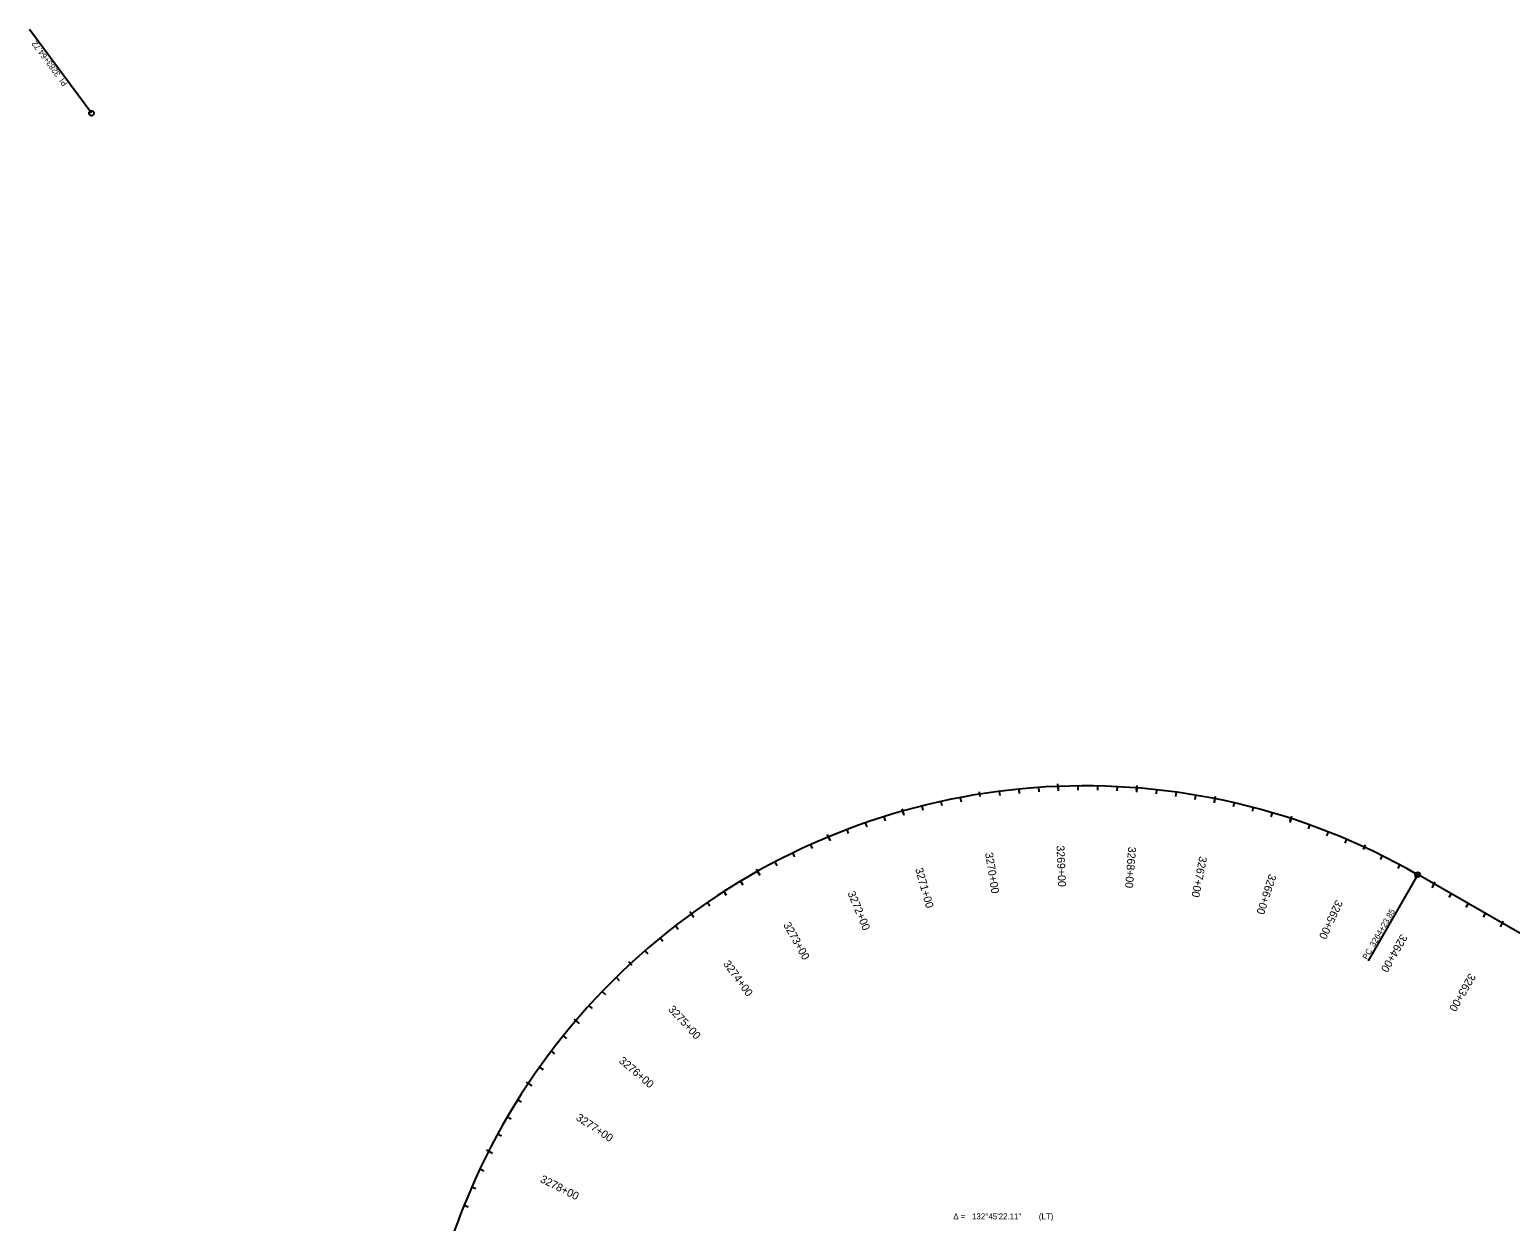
# Model space of a CAD drawing. Extents: x 15451313 to 15455081, y 8857737 to 8860760.
# Drawn here: x 15451313 to 15453192, y 8859247 to 8860760 of the extents above; entities that cross this region are included whole.
import ezdxf

# ---------------------------------------------------------------- set-up
doc = ezdxf.new("R2010")
doc.units = 0
for name, color, linetype in [('Annotation', 7, 'Continuous'), ('PC_REVISION_ANNOTATION', 7, 'Continuous'), ('SheetAddenda', 7, 'Continuous'), ('TextNonPlot', 7, 'Continuous')]:
    doc.layers.add(name, color=color, linetype=linetype)

msp = doc.modelspace()

# ---------------------------------------------------------------- linework, layer by layer
at = {"layer": 'Annotation'}
msp.add_line((15453768, 8859288.8), (15453074.6, 8859687), dxfattribs=at)
msp.add_arc((15452651.9, 8858950.9), 848.8, 60.1345, 192.8906, dxfattribs=at)
at = {"layer": 'PC_REVISION_ANNOTATION'}
for p, q in [((15452494.1, 8859784.9), (15452495.2, 8859779.5)), ((15452519.2, 8859786.2), (15452518.3, 8859792.2)), ((15452543.5, 8859792.7), (15452544.2, 8859787.3)), ((15452568.4, 8859795.6), (15452568.9, 8859790.1)), ((15452593.3, 8859797.7), (15452593.6, 8859792.2)), ((15452618.3, 8859796), (15452618.1, 8859802.1)), ((15452643.2, 8859799.6), (15452643.3, 8859794.2)), ((15452668.2, 8859799.5), (15452668.1, 8859794.1)), ((15452693.2, 8859798.7), (15452692.9, 8859793.2)), ((15452717.9, 8859794.1), (15452718.4, 8859800.2)), ((15452743, 8859794.8), (15452742.5, 8859789.4)), ((15452767.9, 8859791.7), (15452767.1, 8859786.3)), ((15452792.6, 8859788), (15452791.7, 8859782.6)), ((15452816.6, 8859780.4), (15452817.8, 8859786.5)), ((15452422, 8859764.8), (15452420.3, 8859770.7)), ((15452445.3, 8859774.2), (15452446.6, 8859768.9)), ((15452469.6, 8859779.9), (15452470.8, 8859774.6)), ((15452841.6, 8859778.2), (15452840.4, 8859772.9)), ((15452865.9, 8859772.3), (15452864.5, 8859767)), ((15452890, 8859765.6), (15452888.4, 8859760.4)), ((15452373.5, 8859752.7), (15452375.3, 8859747.6)), ((15452397.2, 8859760.6), (15452398.8, 8859755.4)), ((15452912.9, 8859755.3), (15452914.8, 8859761.2)), ((15452937.5, 8859750.2), (15452935.7, 8859745.1)), ((15452327.9, 8859732.1), (15452325.6, 8859737.8)), ((15452350, 8859744.2), (15452351.9, 8859739.1)), ((15452960.9, 8859741.4), (15452959, 8859736.4)), ((15452984.1, 8859732), (15452982, 8859727)), ((15452281.2, 8859714.4), (15452283.5, 8859709.5)), ((15452303.8, 8859725), (15452306, 8859720)), ((15453005.7, 8859719.1), (15453008.2, 8859724.7)), ((15453029.5, 8859711.1), (15453027.1, 8859706.2)), ((15452238.3, 8859688.6), (15452235.3, 8859694)), ((15452258.8, 8859703.2), (15452261.4, 8859698.3)), ((15453051.7, 8859699.6), (15453049.2, 8859694.8)), ((15452215.2, 8859678.7), (15452218, 8859674.1)), ((15453073.6, 8859687.5), (15453070.9, 8859682.8)), ((15453093.8, 8859672.4), (15453096.8, 8859677.7)), ((15452194, 8859665.6), (15452196.9, 8859661)), ((15453117, 8859662.6), (15453114.2, 8859657.9)), ((15452154.5, 8859634.9), (15452150.9, 8859639.8)), ((15452173.1, 8859651.8), (15452176.2, 8859647.3)), ((15453138.6, 8859650.2), (15453135.9, 8859645.5)), ((15453160.3, 8859637.7), (15453157.6, 8859633)), ((15452132.7, 8859622.4), (15452136, 8859618)), ((15453180.5, 8859622.6), (15453183.5, 8859627.9)), ((15452113.1, 8859606.8), (15452116.6, 8859602.6)), ((15452094.1, 8859590.6), (15452097.6, 8859586.5)), ((15452077.5, 8859571.7), (15452073.4, 8859576.2)), ((15452057.4, 8859556.7), (15452061.2, 8859552.8)), ((15452039.8, 8859538.9), (15452043.7, 8859535.1)), ((15452008.6, 8859499.9), (15452003.9, 8859503.8)), ((15452022.7, 8859520.6), (15452026.8, 8859517)), ((15451990.3, 8859482.6), (15451994.5, 8859479.2)), ((15451974.9, 8859462.9), (15451979.3, 8859459.6)), ((15451960.1, 8859442.7), (15451964.6, 8859439.6)), ((15451948.5, 8859420.4), (15451943.4, 8859423.8)), ((15451932.4, 8859401.1), (15451937, 8859398.3)), ((15451919.4, 8859379.8), (15451924.1, 8859377)), ((15451907.1, 8859358), (15451911.9, 8859355.4)), ((15451898.2, 8859334.5), (15451892.7, 8859337.3)), ((15451884.4, 8859313.5), (15451889.4, 8859311.1)), ((15451874.1, 8859290.7), (15451879.1, 8859288.5)), ((15451864.4, 8859267.6), (15451869.5, 8859265.6))]:
    msp.add_line(p, q, dxfattribs=at)
at = {"layer": 'SheetAddenda'}
for p, q in [((15452519.2, 8859786.2), (15452518.3, 8859792.2)), ((15452618.2, 8859799), (15452618.4, 8859793.6)), ((15452718.1, 8859797.1), (15452717.7, 8859791.7)), ((15452421.2, 8859767.7), (15452422.6, 8859762.5)), ((15452817.2, 8859783.5), (15452816.1, 8859778.1)), ((15452913.9, 8859758.3), (15452912.2, 8859753.1)), ((15452326.7, 8859734.9), (15452328.8, 8859729.9)), ((15453005.7, 8859719.1), (15453008.2, 8859724.7)), ((15452236.8, 8859691.3), (15452239.5, 8859686.5)), ((15453095.3, 8859675.1), (15453092.6, 8859670.4)), ((15452152.7, 8859637.4), (15452155.9, 8859632.9)), ((15453182, 8859625.3), (15453179.3, 8859620.6)), ((15452077.5, 8859571.7), (15452073.4, 8859576.2)), ((15452006.2, 8859501.9), (15452010.4, 8859498.3)), ((15451945.9, 8859422.1), (15451950.5, 8859419.1)), ((15451895.4, 8859335.9), (15451900.3, 8859333.4))]:
    msp.add_line(p, q, dxfattribs=at)
at = {"layer": 'TextNonPlot'}
for p, q in [((15451391.5, 8860653.4), (15451312.9, 8860759.5)), ((15451312.9, 8860759.5), (15451312.9, 8860759.5)), ((15453074.6, 8859687), (15453011.9, 8859577.7)), ((15453011.9, 8859577.7), (15453011.9, 8859577.7))]:
    msp.add_line(p, q, dxfattribs=at)
for centre in [(15451391.5, 8860653.4), (15453074.6, 8859687)]:
    msp.add_circle(centre, 3.12, dxfattribs=at)

# ---------------------------------------------------------------- texts
at = {"layer": 'PC_REVISION_ANNOTATION'}
for s, rotation, p in [('3270+00', 279.0246, (15452525.6, 8859714.3)), ('3269+00', 272.2746, (15452616.2, 8859723.9)), ('3268+00', 265.5247, (15452707.3, 8859722.7)), ('3267+00', 258.7747, (15452797.6, 8859710.9)), ('3271+00', 285.7746, (15452436.7, 8859694.2)), ('3266+00', 252.0247, (15452886, 8859688.5)), ('3272+00', 292.5245, (15452350.8, 8859663.7)), ('3265+00', 245.2747, (15452971, 8859655.8)), ('3273+00', 299.2745, (15452269.1, 8859623.4)), ('3264+00', 240.1345, (15453053.6, 8859612.5)), ('3274+00', 306.0245, (15452192.7, 8859573.8)), ('3263+00', 240.1345, (15453140.3, 8859562.7)), ('3275+00', 312.7744, (15452122.7, 8859515.5)), ('3276+00', 319.5244, (15452060, 8859449.4)), ('3277+00', 326.2744, (15452005.5, 8859376.3)), ('3278+00', 333.0244, (15451960, 8859297.4))]:
    msp.add_text(s, height=10.02, rotation=rotation, dxfattribs=at).set_placement(p)
at = {"layer": 'SheetAddenda'}
for s, rotation, p in [('3270+00', 279.0246, (15452525.6, 8859714.3)), ('3265+00', 245.2747, (15452971, 8859655.8)), ('3275+00', 312.7744, (15452122.7, 8859515.5))]:
    msp.add_text(s, height=10.02, rotation=rotation, dxfattribs=at).set_placement(p)
at = {"layer": 'TextNonPlot'}
for s, rotation, p in [('3283+64.72', 126.5126, (15451352.6, 8860703.2)), ('PI ', 126.5126, (15451361.5, 8860691.2)), ('3264+23.85', 60.1345, (15453019.7, 8859594.7)), ('PC', 60.1345, (15453010.4, 8859578.5))]:
    msp.add_text(s, height=7.5, rotation=rotation, dxfattribs=at).set_placement(p)
for s, p in [('Δ = ', (15452485.2, 8859249.5)), ('132°45\'22.11"', (15452509, 8859249.5)), (' (LT)', (15452591, 8859249.5))]:
    msp.add_text(s, height=7.5, dxfattribs=at).set_placement(p)

doc.saveas('drawing.dxf')
